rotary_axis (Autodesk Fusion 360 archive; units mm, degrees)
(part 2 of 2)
sketch "Sketch2" plane through (0, 0, 3) normal (0, 0, 1) x axis (-1, 0, 0)
  line L1 (0, -1.4434) -> (-1.25, -0.7217)
  line L2 (1.25, -0.7217) -> (0, -1.4434)
  line L3 (1.25, 0.7217) -> (1.25, -0.7217)
  line L4 (0, 1.4434) -> (1.25, 0.7217)
  line L5 (-1.25, 0.7217) -> (0, 1.4434)
  line L6 (-1.25, -0.7217) -> (-1.25, 0.7217)
  circle C1 centre (0, 0) radius 2.75
  point P1 (0, 0)
  point P9 (0, 0)
  point P5 (1.25, -0.7217)
  coincident P1 P9
  vertical L6
  dimension "d8" distance P5 L6 = 2.5
extrude "Extrude1" cut sketch "Sketch2" profile of L1 L2 L3 L4 L5 L6 against normal blind 2

design "HW_M5x20-FHCS"
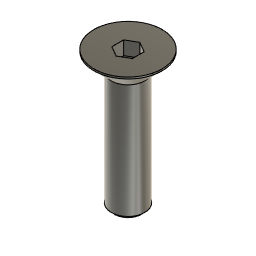
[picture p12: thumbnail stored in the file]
sketch "Sketch1" plane through (0, 0, 0) normal (0, 1, 0) x axis (1, 0, 0)
  line L1 (0, 20) -> (0, 0)
  line L2 (1.95, 20) -> (0, 20)
  line L3 (2.45, 19.5) -> (1.95, 20)
  line L4 (2.45, 2.8) -> (2.45, 19.5)
  line L5 (5, 0.25) -> (2.45, 2.8)
  line L6 (5, 0) -> (5, 0.25)
  line L7 (0, 0) -> (5, 0)
  point P1 (0, 0)
  point P2 (0, 0)
  point P9 (0, 0)
  point P3 (0, 20)
  point P4 (1.95, 20)
  point P8 (5, 0)
  point P7 (5, 0.25)
  coincident P1 P2
  vertical L1
  perpendicular L1 L2
  perpendicular L2 L4
  parallel L3 L5
  parallel L4 L6
  perpendicular L6 L7
  coincident P1 P9
  dimension "d1" distance P3 L4 = 2.45 (= "( 4.9 / 2 ) * 1 mm")
  dimension "d3" angle L2 L3 = 45
  dimension "d5" distance P4 L4 = 0.5
  dimension "d6" distance P2 P3 = 20
  dimension "d7" distance P8 P9 = 5 (= "( 10 / 2 ) * 1 mm")
  dimension "d9" distance P7 P8 = 0.25
revolve "Revolve1" sketch "Sketch1" AlongAngle 360
sketch "Sketch2" plane through (0, 0, 0) normal (0, 0, 1) x axis (-1, 0, 0)
  line L1 (0, -1.7321) -> (-1.5, -0.866)
  line L2 (1.5, -0.866) -> (0, -1.7321)
  line L3 (1.5, 0.866) -> (1.5, -0.866)
  line L4 (0, 1.7321) -> (1.5, 0.866)
  line L5 (-1.5, 0.866) -> (0, 1.7321)
  line L6 (-1.5, -0.866) -> (-1.5, 0.866)
  circle C1 centre (0, 0) radius 5
  point P1 (0, 0)
  point P9 (0, 0)
  coincident P1 P9
  vertical L6
  dimension "d12" distance L3 L6 = 3
extrude "Extrude1" cut sketch "Sketch2" profile of L1 L2 L3 L4 L5 L6 against normal blind 2

design "PP_ACTU_N17-Stepper"
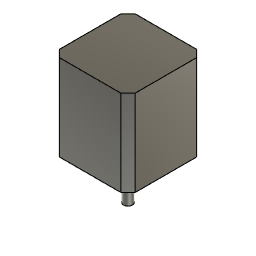
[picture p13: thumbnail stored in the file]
description: Nema 17 Stepper, 48mm Length Preferred, 5mm Shaft
sketch "Sketch1" plane through (0, 0, 0) normal (0, 0, 1) x axis (1, 0, 0)
  line L1 (-21.15, 21.15) -> (21.15, 21.15)
  line L2 (-21.15, -21.15) -> (-21.15, 21.15)
  line L3 (21.15, -21.15) -> (-21.15, -21.15)
  line L4 (21.15, 21.15) -> (21.15, -21.15)
  line L5 (-21.15, -21.15) -> (21.15, 21.15)
  line L6 (21.15, -21.15) -> (-21.15, 21.15)
  line L7 (15.5, 15.5) -> (-15.5, 15.5)
  line L8 (15.5, -15.5) -> (15.5, 15.5)
  line L9 (-15.5, -15.5) -> (15.5, -15.5)
  line L10 (-15.5, 15.5) -> (-15.5, -15.5)
  circle C1 centre (0, 0) radius 11
  circle C2 centre (-15.5, 15.5) radius 1.5
  circle C3 centre (-15.5, -15.5) radius 1.5
  circle C4 centre (15.5, -15.5) radius 1.5
  circle C5 centre (15.5, 15.5) radius 1.5
  circle C6 centre (0, 0) radius 2.5
  point P6 (0, 0)
  point P1 (0, 0)
  point P7 (0, 0)
  point P10 (15.5, -15.5)
  point P8 (-15.5, 15.5)
  point P9 (15.5, 15.5)
  point P12 (-15.5, 15.5)
  point P11 (-15.5, -15.5)
  point P13 (-15.5, -15.5)
  point P14 (15.5, -15.5)
  point P15 (15.5, 15.5)
  point P2 (21.15, 21.15)
  point P3 (-21.15, 21.15)
  perpendicular L1 L2
  parallel L1 L3
  parallel L2 L4
  horizontal L1
  coincident L5 P6
  coincident L6 P6
  coincident P1 P6
  equal L1 L2
  coincident P6 P7
  horizontal L7
  vertical L8
  horizontal L9
  vertical L10
  coincident L6 P10
  coincident L6 P8
  coincident L5 P9
  coincident P8 P12
  coincident P11 P13
  coincident P10 P14
  coincident P9 P15
  equal C2 C5
  equal C2 C3
  equal C2 C4
  concentric C1 C6
  dimension "d1" distance P2 P3 = 42.3
  dimension "d2" diameter C1 = 22
  dimension "d3" distance P8 P9 = 31
  dimension "d4" diameter C2 = 3
  dimension "d5" diameter C6 = 5
  dimension "d19" alignAngle = 0
  dimension "d20" alignOffsetX = 0
  dimension "d21" alignOffsetY = 0
  dimension "d22" alignOffsetZ = 0
  dimension "d23" alignAngle = 180
  dimension "d24" alignOffsetX = 0
  dimension "d25" alignOffsetY = 0
  dimension "d26" alignOffsetZ = 0
extrude "Extrude1" new body sketch "Sketch1" profile of L1 L2 L3 L4 C1 C2 C3 C4 C5 C6 along normal blind 48
extrude "Extrude2" cut sketch "Sketch1" profile of C2 C3 C4 C5 along normal blind 5
extrude "Extrude3" add sketch "Sketch1" profile of C1 C6 against normal blind 2
extrude "Extrude4" add sketch "Sketch1" profile of C6 against normal blind 24
chamfer "Chamfer1" distance 4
